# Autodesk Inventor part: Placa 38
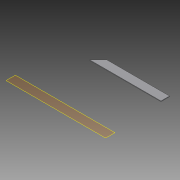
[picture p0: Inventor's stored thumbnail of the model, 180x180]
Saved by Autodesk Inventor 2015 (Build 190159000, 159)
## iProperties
Created: 2015-04
Part Number: Placa 38
Material: Generic
Document SubType Name: Modeling
Designer: suporte
Density: 1 g/cm^3
Appearance: Default
Author: suporte
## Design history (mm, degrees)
workplane "Work Plane1"
sketch "Sketch1"
  geometry: L1 (-456.261, 975)-(-459.764, 971.499) reference; L2 (-418.362, 1125)-(100.237, 1125) reference; L3 (800, -575)-(800, 1225) reference; L4 (-434.236, 975)-(-439.764, 975) reference; L5 (-518.362, 1125)-(-800, 843.558) reference; L6 (-456.261, 975)-(-306.156, 1125); L7 (-306.156, 1125)-(800, 1125); L8 (-456.261, 975)-(800, 975); L9 (800, 975)-(800, 1125); 1 further point
  constraints: 8 end point, 3 point on line, 2 collinear, 2 perpendicular
extrude "Extrusion1" new body sketch "Sketch1" distance "d0" = 12.5; taper "d1" = 0 deg
body "Solid1"
node "Reference1"
node "Reference2"
node "Reference3"
node "Reference4"
node "Reference5"
